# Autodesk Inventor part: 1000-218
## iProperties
Created: 2007-03
Part Number: 1000-218
Document SubType Name: Modeling
Designer: Andy Moles
Material: Steel
Mass: 69.1773 g
Surface Area: 56.9046 cm^2
Volume: 8.81239 cm^3
Density: 7.85 g/cm^3
Author: Andy Moles
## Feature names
1. Base1
